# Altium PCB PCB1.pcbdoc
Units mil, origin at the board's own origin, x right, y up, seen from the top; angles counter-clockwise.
Board outline 2086.61 x 4488.19 mil, 2 copper layers (Top Layer, Bottom Layer); 30 components, 21 nets, 60 pads, 167 vias.
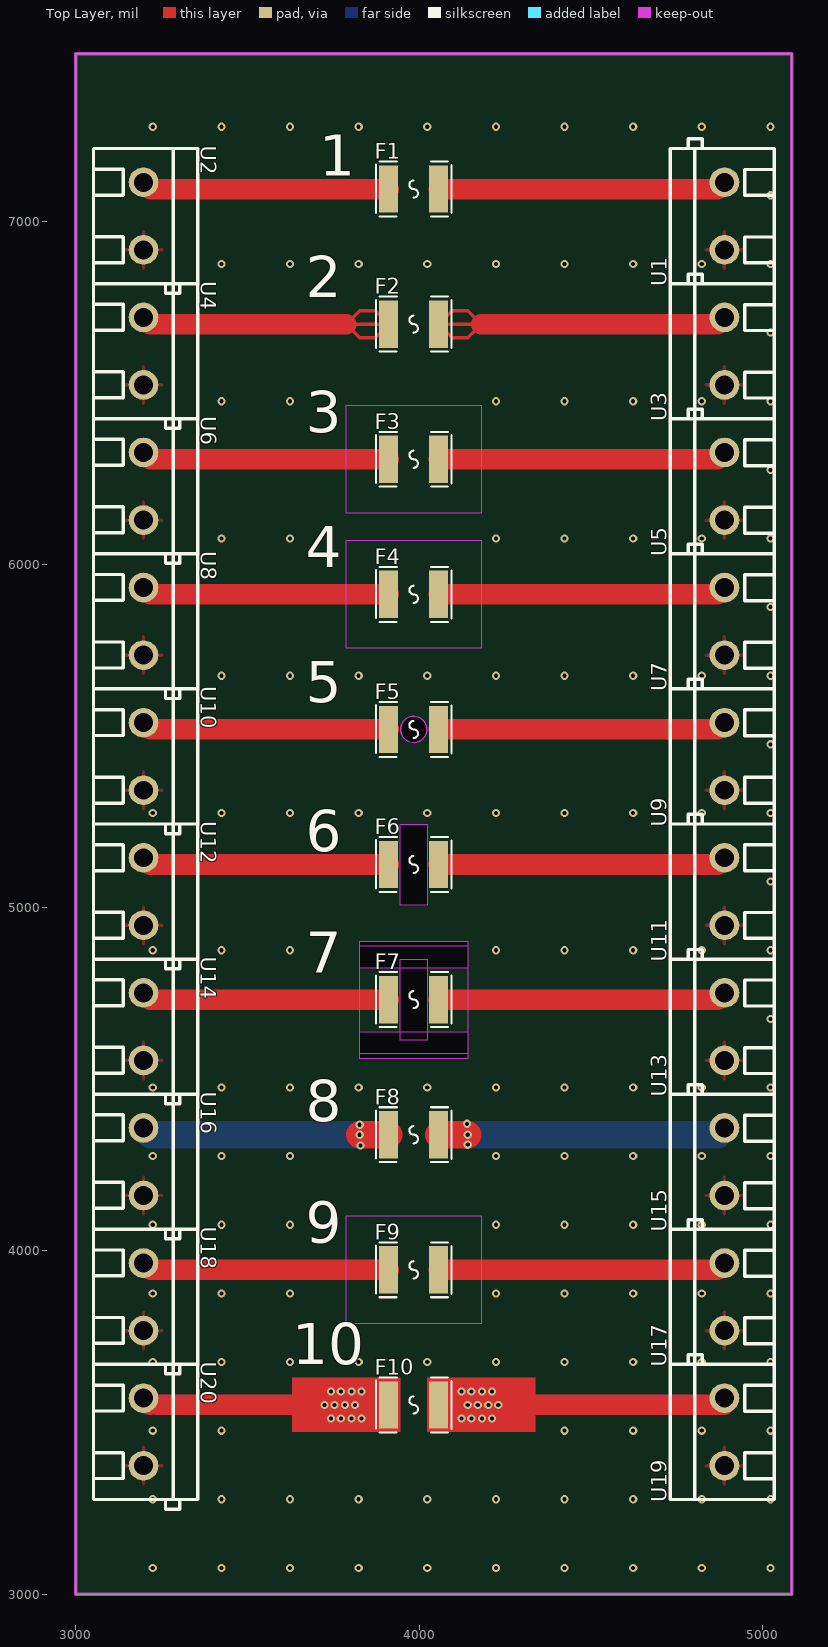
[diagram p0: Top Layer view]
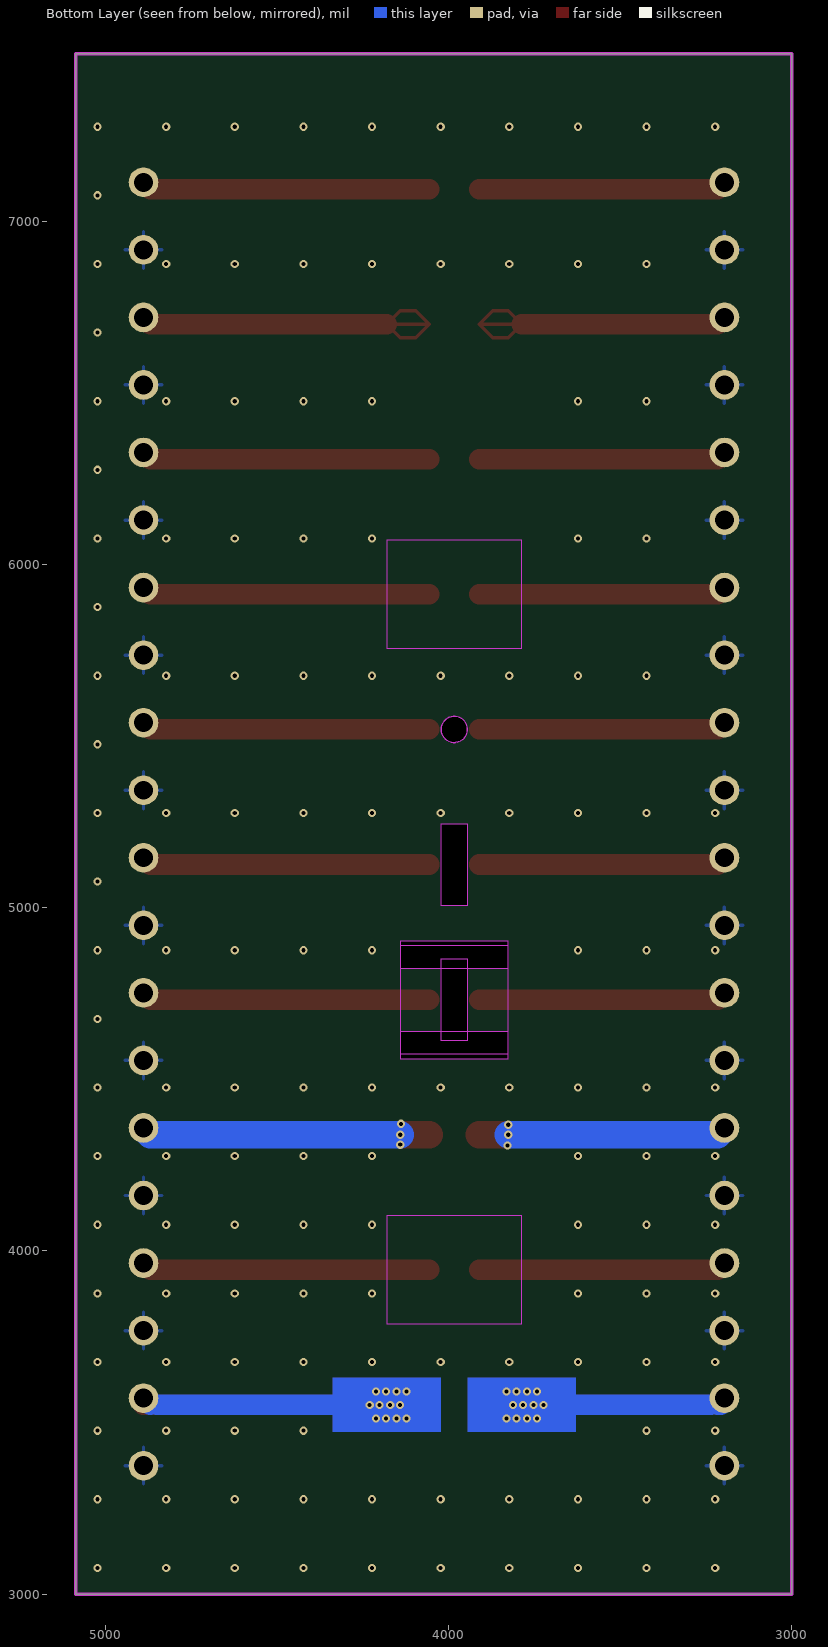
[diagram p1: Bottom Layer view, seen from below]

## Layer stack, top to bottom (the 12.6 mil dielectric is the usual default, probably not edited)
Top Layer: signal copper (thickness not stored)
Dielectric: dielectric 12.6, FR-4, Dk 4.8
Bottom Layer: signal copper (thickness not stored)

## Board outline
3000,7488.19 5086.61,7488.19 5086.61,3000 3000,3000
cut-out: 4022.47,5519.69 cw(c3984.25,5519.69) 3946.04,5519.69 cw(c3984.25,5519.69)
cut-out: 3944.88,5244.09 4023.62,5244.09 4023.62,5007.87 3944.88,5007.87
cut-out: 3944.88,4850.39 4023.62,4850.39 4023.62,4614.17 3944.88,4614.17
cut-out: 3826.77,4823.45 3826.77,4902.19 4141.73,4902.19 4141.73,4823.45
cut-out: 3826.77,4559.36 3826.77,4638.1 4141.73,4638.1 4141.73,4559.36

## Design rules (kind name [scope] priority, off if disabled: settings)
BoardOutlineClearance copperThickness1oz [All] p0: genericclearance=10 ignorepadtopadclearanceinfootprint=FALSE except(0: Arc-SplitContinuation Track-SplitContinuation SMDPad-SplitContinuation THPad-SplitContinuation Via-SplitContinuation Fill-SplitContinuation Poly-SplitContinuation Region-SplitContinuation Text-SplitContinuation; 6: Track-CutoutEdge SMDPad-CutoutEdge THPad-CutoutEdge Via-CutoutEdge Region-CutoutEdge; 11.8: Track-OutlineEdge SMDPad-OutlineEdge THPad-OutlineEdge Via-OutlineEdge Fill-OutlineEdge Region-OutlineEdge Poly-OutlineEdge Text-OutlineEdge Fill-CutoutEdge)
BoardOutlineClearance copperThickness2oz [All] p0: genericclearance=10 ignorepadtopadclearanceinfootprint=FALSE except(0: Arc-SplitContinuation Track-SplitContinuation SMDPad-SplitContinuation THPad-SplitContinuation Via-SplitContinuation Fill-SplitContinuation Poly-SplitContinuation Region-SplitContinuation Text-SplitContinuation; 6: Track-CutoutEdge SMDPad-CutoutEdge THPad-CutoutEdge Via-CutoutEdge Region-CutoutEdge; 11.8: Track-OutlineEdge SMDPad-OutlineEdge THPad-OutlineEdge Via-OutlineEdge Fill-OutlineEdge Region-OutlineEdge Poly-OutlineEdge Text-OutlineEdge Fill-CutoutEdge)
Clearance copperThickness1oz [(InNet('$1N279') OR InNet('$1N275') OR InNet('$1N479') OR InNet('$1N477') OR InNet('$1N640') OR InNet('$1N638') OR InNet('$1N801') OR InNet('$1N799') OR InNet('$1N962') OR InNet('$1N960') OR InNet('$1N1719') OR InNet('$1N1717') OR InNet('$1N1729') OR InNet('$1N1727') OR InNet('$1N1739') OR InNet('$1N1737') OR InNet('$1N1749') OR InNet('$1N1747') OR InNet('$1N1759') OR InNet('$1N1757') OR InNet('GND'))] p1: gap=7 ignorepadtopadclearanceinfootprint=FALSE except(4: Track-Track; 6: Track-SMDPad SMDPad-SMDPad Track-THPad SMDPad-THPad THPad-THPad Track-Via SMDPad-Via THPad-Via Via-Via SMDPad-Fill THPad-Fill Via-Fill Fill-Fill Track-Region SMDPad-Region THPad-Region Via-Region Region-Region Track-Poly SMDPad-Poly THPad-Poly Via-Poly Fill-Poly Region-Poly Poly-Poly Track-Text SMDPad-Text THPad-Text Via-Text Fill-Text Region-Text Poly-Text Text-Text; 6.9: Track-Hole SMDPad-Hole THPad-Hole Via-Hole Fill-Hole Region-Hole Poly-Hole Text-Hole Sheet-Hole; 11.8: Track-Fill Fill-Region Track-Sheet SMDPad-Sheet THPad-Sheet Via-Sheet Fill-Sheet Region-Sheet Poly-Sheet Text-Sheet)
Clearance copperThickness2oz [All] p1: gap=7 ignorepadtopadclearanceinfootprint=FALSE except(6: Track-SMDPad SMDPad-SMDPad Track-THPad SMDPad-THPad THPad-THPad Track-Via SMDPad-Via THPad-Via Via-Via SMDPad-Fill THPad-Fill Via-Fill Fill-Fill Track-Region SMDPad-Region THPad-Region Via-Region Region-Region Track-Poly SMDPad-Poly THPad-Poly Via-Poly Fill-Poly Region-Poly Poly-Poly Track-Text SMDPad-Text THPad-Text Via-Text Fill-Text Region-Text Poly-Text Text-Text; 6.9: Track-Hole SMDPad-Hole THPad-Hole Via-Hole Fill-Hole Region-Hole Poly-Hole Text-Hole Sheet-Hole; 8: Track-Track; 11.8: Track-Fill Fill-Region Track-Sheet SMDPad-Sheet THPad-Sheet Via-Sheet Fill-Sheet Region-Sheet Poly-Sheet Text-Sheet)
DiffPairsRouting differentialPair [All] p1: maxuncoupledlength=10 minlimit=6 maxlimit=6 mostfreqgap=6 toplayer_minwidth=5 toplayer_prefwidth=10 toplayer_maxwidth=100 bottomlayer_minwidth=5 bottomlayer_prefwidth=10 bottomlayer_maxwidth=100
PasteMaskExpansion pasteMaskExpansion [All] p1: expansion=0
PlaneConnect innerPlane [All] p1: planeconnectstyle=Relief reliefexpansion=20 reliefentries=4 reliefconductorwidth=10 reliefairgap=10
PolygonConnect copperRegion [All] p1: connectstyle=Relief reliefentries=4 reliefconductorwidth=10 polygonreliefangle="90 Angle" airgapwidth=10
RoutingVias viaSize [All] p1: viastyle="Through Hole" holewidth=12.0078 minholewidth=11.811 maxholewidth=248.0314 width=24.0158 minwidth=19.685 maxwidth=393.7008
SolderMaskExpansion solderMaskExpansion [All] p1: useseparateexpansions=TRUE expansion=2 expansionbottom=2
Width copperThickness1oz [All] p1: maxlimit=100 minlimit=5 preferedwidth=10
Width copperThickness2oz [All] p1: maxlimit=100 minlimit=8 preferedwidth=10

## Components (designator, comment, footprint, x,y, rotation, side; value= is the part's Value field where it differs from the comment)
F1 "1812L110/33MR" F1812 3984.25,7094.49 r0 top
F2 "1812L110/33MR" F1812 3984.25,6700.79 r0 top
F3 "1812L110/33MR" F1812 3984.25,6307.09 r0 top
F4 "1812L110/33MR" F1812 3984.25,5913.39 r0 top
F5 "1812L110/33MR" F1812 3984.25,5519.69 r0 top
F6 "1812L110/33MR" F1812 3984.25,5125.98 r0 top
F7 "1812L110/33MR" F1812 3984.25,4732.28 r0 top
F8 "1812L110/33MR" F1812 3984.25,4338.58 r0 top
F9 "1812L110/33MR" F1812 3984.25,3944.88 r0 top
F10 "1812L110/33MR" F1812 3984.25,3551.18 r0 top
U1 "KF301-5.0-2P" CONN-TH_P5.00_KF301-5.0-2P 4889.76,7015.75 r90 top
U2 "KF301-5.0-2P" CONN-TH_P5.00_KF301-5.0-2P 3196.85,7015.75 r270 top
U3 "KF301-5.0-2P" CONN-TH_P5.00_KF301-5.0-2P 4889.76,6622.05 r90 top
U4 "KF301-5.0-2P" CONN-TH_P5.00_KF301-5.0-2P 3196.85,6622.05 r270 top
U5 "KF301-5.0-2P" CONN-TH_P5.00_KF301-5.0-2P 4889.76,6228.35 r90 top
U6 "KF301-5.0-2P" CONN-TH_P5.00_KF301-5.0-2P 3196.85,6228.35 r270 top
U7 "KF301-5.0-2P" CONN-TH_P5.00_KF301-5.0-2P 4889.76,5834.65 r90 top
U8 "KF301-5.0-2P" CONN-TH_P5.00_KF301-5.0-2P 3196.85,5834.65 r270 top
U9 "KF301-5.0-2P" CONN-TH_P5.00_KF301-5.0-2P 4889.76,5440.94 r90 top
U10 "KF301-5.0-2P" CONN-TH_P5.00_KF301-5.0-2P 3196.85,5440.94 r270 top
U11 "KF301-5.0-2P" CONN-TH_P5.00_KF301-5.0-2P 4889.76,5047.24 r90 top
U12 "KF301-5.0-2P" CONN-TH_P5.00_KF301-5.0-2P 3196.85,5047.24 r270 top
U13 "KF301-5.0-2P" CONN-TH_P5.00_KF301-5.0-2P 4889.76,4653.54 r90 top
U14 "KF301-5.0-2P" CONN-TH_P5.00_KF301-5.0-2P 3196.85,4653.54 r270 top
U15 "KF301-5.0-2P" CONN-TH_P5.00_KF301-5.0-2P 4889.76,4259.84 r90 top
U16 "KF301-5.0-2P" CONN-TH_P5.00_KF301-5.0-2P 3196.85,4259.84 r270 top
U17 "KF301-5.0-2P" CONN-TH_P5.00_KF301-5.0-2P 4889.76,3866.14 r90 top
U18 "KF301-5.0-2P" CONN-TH_P5.00_KF301-5.0-2P 3196.85,3866.14 r270 top
U19 "KF301-5.0-2P" CONN-TH_P5.00_KF301-5.0-2P 4889.76,3472.44 r90 top
U20 "KF301-5.0-2P" CONN-TH_P5.00_KF301-5.0-2P 3196.85,3472.44 r270 top

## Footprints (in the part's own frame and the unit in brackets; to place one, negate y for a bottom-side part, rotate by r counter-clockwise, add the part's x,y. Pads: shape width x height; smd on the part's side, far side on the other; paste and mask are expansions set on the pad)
CONN-TH_P5.00_KF301-5.0-2P [mm]
  round 2.2 hole 1.4: 1(-2.5,0) 2(2.5,0)
  silkscreen extent -5,-3.7 5.71,4
F1812 [mil]
  rect 55.38x137.76 smd: 1(-72.97,0) 2(72.97,0)
  silkscreen extent -110,-80 110,80

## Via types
v1: diameter 24.02, hole 12.01, Top Layer to Bottom Layer, 167 vias

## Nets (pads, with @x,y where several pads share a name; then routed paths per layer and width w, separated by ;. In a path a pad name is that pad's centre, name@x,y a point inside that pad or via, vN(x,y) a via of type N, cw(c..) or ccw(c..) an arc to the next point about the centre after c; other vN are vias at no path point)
$1N275: F1.1 U2.1 | length 722.6
  Top Layer w60: U2.1 3216.54,7094.49 F1.1
$1N279: F1.2 U1.2 | length 840.7
  Top Layer w60: F1.2 4870.08,7094.49 U1.2
$1N477: F2.1 U4.1 | length 1035.6
  Top Layer w10: 3787.4,6700.79 3826.77,6740.16 3871.91,6740.16 F2.1 ; 3787.4,6700.79 F2.1 ; 3787.4,6700.79 3826.77,6661.42 3871.91,6661.42 F2.1
  Top Layer w60: U4.1 3216.54,6700.79 3787.4,6700.79
$1N479: F2.2 U3.2 | length 1153.7
  Top Layer w10: F2.2 4181.1,6700.79 ; F2.2 4096.59,6740.16 4141.73,6740.16 4181.1,6700.79 ; F2.2 4096.59,6661.42 4141.73,6661.42 4181.1,6700.79
  Top Layer w60: 4181.1,6700.79 4870.08,6700.79 U3.2
$1N638: F3.1 U6.1 | length 722.6
  Top Layer w60: U6.1 3216.54,6307.09 F3.1
$1N640: F3.2 U5.2 | length 840.7
  Top Layer w60: F3.2 4870.08,6307.09 U5.2
$1N799: F4.1 U8.1 | length 722.6
  Top Layer w60: U8.1 3216.54,5913.39 F4.1
$1N801: F4.2 U7.2 | length 840.7
  Top Layer w60: F4.2 4870.08,5913.39 U7.2
$1N960: F5.1 U10.1 | length 722.6
  Top Layer w60: U10.1 3216.54,5519.69 F5.1
$1N962: F5.2 U9.2 | length 840.7
  Top Layer w60: F5.2 4870.08,5519.69 U9.2
$1N1717: F6.1 U12.1 | length 722.6
  Top Layer w60: U12.1 3216.54,5125.98 F6.1
$1N1719: F6.2 U11.2 | length 840.7
  Top Layer w60: F6.2 4870.08,5125.98 U11.2
$1N1727: F7.1 U14.1 | length 722.6
  Top Layer w60: U14.1 3216.54,4732.28 F7.1
$1N1729: F7.2 U13.2 | length 840.7
  Top Layer w60: F7.2 4870.08,4732.28 U13.2
$1N1737: F8.1 U16.1 | length 722.6
  Top Layer w80: v1(3826.77,4338.58) F8.1
  Bottom Layer w80: U16.1 3216.54,4338.58 v1(3826.77,4338.58)
  other v1: 3829,4306.97 3826.77,4367.58
$1N1739: F8.2 U15.2 | length 840.7
  Top Layer w80: F8.2 v1(4141.73,4338.58)
  Bottom Layer w80: v1(4141.73,4338.58) 4870.08,4338.58 U15.2
  other v1: 4141.73,4309.58 4139.5,4370.2
$1N1747: F9.1 U18.1 | length 722.6
  Top Layer w60: U18.1 3216.54,3944.88 F9.1
$1N1749: F9.2 U17.2 | length 840.7
  Top Layer w60: F9.2 4870.08,3944.88 U17.2
$1N1757: F10.1 U20.1 | length 1040.1
  Top Layer w60: U20.1 U20.1@3216.54,3551.18 ; 3236.22,3551.18 v1(3724.35,3551.18)
  Bottom Layer w60: U20.1@3188.66,3570.87 3208.35,3551.18 U20.1@3216.54,3551.18 ; 3236.22,3551.18 v1(3724.35,3551.18)
  other v1: 3743,3511.81 3772,3511.81 3802.8,3511.81 3831.8,3511.81 3753.35,3551.18 3784.14,3551.18 3813.15,3551.18 3743,3590.55 3772,3590.55 3802.8,3590.55 3831.8,3590.55
$1N1759: F10.2 U19.2 | length 1362.2
  Top Layer w60: v1(4230.73,3551.18) U19.2@4870.08,3551.18 ; U19.2@4889.76,3551.18 U19.2@4870.09,3551.18 ; U19.2@4870.08,3551.18 U19.2 U19.2@4870.09,3551.18
  Bottom Layer w60: v1(4230.73,3551.18) 4850.39,3551.18 ; U19.2@4870.08,3551.18 U19.2
  other v1: 4123.28,3511.81 4152.28,3511.81 4183.07,3511.81 4212.07,3511.81 4141.93,3551.18 4170.93,3551.18 4201.73,3551.18 4123.28,3590.55 4152.28,3590.55 4183.07,3590.55 4212.07,3590.55
GND: U1.1 U2.2 U3.1 U4.2 U5.1 U6.2 U7.1 U8.2 U9.1 U10.2 U11.1 U12.2 U13.1 U14.2 U15.1 U16.2 U17.1 U18.2 U19.1 U20.2
  other v1: 3223.77,3076.18 3423.77,3076.18 3623.77,3076.18 3823.77,3076.18 4023.77,3076.18 4223.77,3076.18 4423.77,3076.18 4623.77,3076.18 4823.77,3076.18 5023.77,3076.18 3223.77,3276.18 3423.77,3276.18 3623.77,3276.18 3823.77,3276.18 4023.77,3276.18 4223.77,3276.18 4423.77,3276.18 4623.77,3276.18 4823.77,3276.18 5023.77,3276.18 3223.77,3476.18 3423.77,3476.18 4423.77,3476.18 4623.77,3476.18 4823.77,3476.18 5023.77,3476.18 3223.77,3676.18 3423.77,3676.18 3623.77,3676.18 3823.77,3676.18 4023.77,3676.18 4223.77,3676.18 4423.77,3676.18 4623.77,3676.18 4823.77,3676.18 5023.77,3676.18 3223.77,3876.18 3423.77,3876.18 3623.77,3876.18 4223.77,3876.18 4423.77,3876.18 4623.77,3876.18 4823.77,3876.18 5023.77,3876.18 3223.77,4076.18 3423.77,4076.18 3623.77,4076.18 4223.77,4076.18 4423.77,4076.18 4623.77,4076.18 4823.77,4076.18 5023.77,4076.18 3223.77,4276.18 3423.77,4276.18 3623.77,4276.18 4223.77,4276.18 4423.77,4276.18 4623.77,4276.18 4823.77,4276.18 5023.77,4276.18 3223.77,4476.18 3423.77,4476.18 3623.77,4476.18 3823.77,4476.18 4023.77,4476.18 4223.77,4476.18 4423.77,4476.18 4623.77,4476.18 4823.77,4476.18 5023.77,4476.18 5023.77,4676.18 3223.77,4876.18 3423.77,4876.18 3623.77,4876.18 4223.77,4876.18 4423.77,4876.18 4623.77,4876.18 4823.77,4876.18 5023.77,4876.18 5023.77,5076.18 3223.77,5276.18 3423.77,5276.18 3623.77,5276.18 3823.77,5276.18 4023.77,5276.18 4223.77,5276.18 4423.77,5276.18 4623.77,5276.18 4823.77,5276.18 5023.77,5276.18 5023.77,5476.18 3423.77,5676.18 3623.77,5676.18 3823.77,5676.18 4023.77,5676.18 4223.77,5676.18 4423.77,5676.18 4623.77,5676.18 4823.77,5676.18 5023.77,5676.18 5023.77,5876.18 3423.77,6076.18 3623.77,6076.18 4223.77,6076.18 4423.77,6076.18 4623.77,6076.18 4823.77,6076.18 5023.77,6076.18 5023.77,6276.18 3423.77,6476.18 3623.77,6476.18 4223.77,6476.18 4423.77,6476.18 4623.77,6476.18 4823.77,6476.18 5023.77,6476.18 5023.77,6676.18 3423.77,6876.18 3623.77,6876.18 3823.77,6876.18 4023.77,6876.18 4223.77,6876.18 4423.77,6876.18 4623.77,6876.18 4823.77,6876.18 5023.77,6876.18 5023.77,7076.18 3223.77,7276.18 3423.77,7276.18 3623.77,7276.18 3823.77,7276.18 4023.77,7276.18 4223.77,7276.18 4423.77,7276.18 4623.77,7276.18 4823.77,7276.18 5023.77,7276.18

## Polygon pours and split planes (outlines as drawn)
GND on Top Layer (solid, remove dead copper, pour order 0): 3000,7488.19 5086.61,7488.19 5086.61,3000 3000,3000
GND on Bottom Layer (solid, remove dead copper, pour order 2): 3000,7488.19 5086.61,7488.19 5086.61,3000 3000,3000

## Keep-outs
Top Layer:
  region: 3787.4,6464.57 4181.1,6464.57 4181.1,6149.61 3787.4,6149.61
Board Outline Layer:
  circle w1: c3984.25,5519.69 r38.22
  region: 4022.47,5519.69 cw(c3984.25,5519.69) 3946.04,5519.69 cw(c3984.25,5519.69)
  region: 3787.4,6070.87 4181.1,6070.87 4181.1,5755.91 3787.4,5755.91
  region: 3944.88,5244.09 4023.62,5244.09 4023.62,5007.87 3944.88,5007.87
  region: 3944.88,4850.39 4023.62,4850.39 4023.62,4614.17 3944.88,4614.17
  region: 3826.77,4823.45 3826.77,4902.19 4141.73,4902.19 4141.73,4823.45
  region: 3826.77,4559.36 3826.77,4638.1 4141.73,4638.1 4141.73,4559.36
  region: 3826.77,4889.76 4141.73,4889.76 4141.73,4574.8 3826.77,4574.8
  region: 3787.4,4102.36 4181.1,4102.36 4181.1,3787.4 3787.4,3787.4
  lines w1: 3826.77,4559.36 3826.77,4638.1 4141.73,4638.1 4141.73,4559.36 3826.77,4559.36 ; 3826.77,4823.45 3826.77,4902.19 4141.73,4902.19 4141.73,4823.45 3826.77,4823.45 ; 3944.88,4614.17 4023.62,4614.17 4023.62,4850.39 3944.88,4850.39 3944.88,4614.17 ; 3944.88,5007.87 4023.62,5007.87 4023.62,5244.09 3944.88,5244.09 3944.88,5007.87
  lines w10: 3000,3000 5086.61,3000 5086.61,7488.19 3000,7488.19 3000,3000

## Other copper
Top Layer:
  region net $1N1757: 3629.92,3629.92 3944.88,3629.92 3944.88,3472.44 3629.92,3472.44
  region net $1N1759: 4338.59,3472.44 4023.63,3472.44 4023.63,3629.92 4338.59,3629.92
Bottom Layer:
  region net $1N1757: 3629.92,3629.92 3944.88,3629.92 3944.88,3472.44 3629.92,3472.44
  region net $1N1759: 4338.59,3472.44 4023.63,3472.44 4023.63,3629.92 4338.59,3629.92

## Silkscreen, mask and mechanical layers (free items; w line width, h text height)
Top Silkscreen Layer:
  text "1" at 3708.66,7133.86 h120
  text "2" at 3669.29,6779.53 h120
  text "3" at 3669.29,6385.83 h120
  text "4" at 3669.29,5992.13 h120
  text "5" at 3669.29,5598.43 h120
  text "6" at 3669.29,5165.35 h120
  text "7" at 3669.29,4811.02 h120
  text "8" at 3669.29,4377.95 h120
  text "9" at 3669.29,4023.62 h120
  text "10" at 3629.92,3669.29 h120
Mechanical Layer:
  circle w1: c3984.25,5519.69 r38.22
  lines w1: 3826.77,4559.36 3826.77,4638.1 4141.73,4638.1 4141.73,4559.36 3826.77,4559.36 ; 3826.77,4823.45 3826.77,4902.19 4141.73,4902.19 4141.73,4823.45 3826.77,4823.45 ; 3944.88,4614.17 4023.62,4614.17 4023.62,4850.39 3944.88,4850.39 3944.88,4614.17 ; 3944.88,5007.87 4023.62,5007.87 4023.62,5244.09 3944.88,5244.09 3944.88,5007.87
